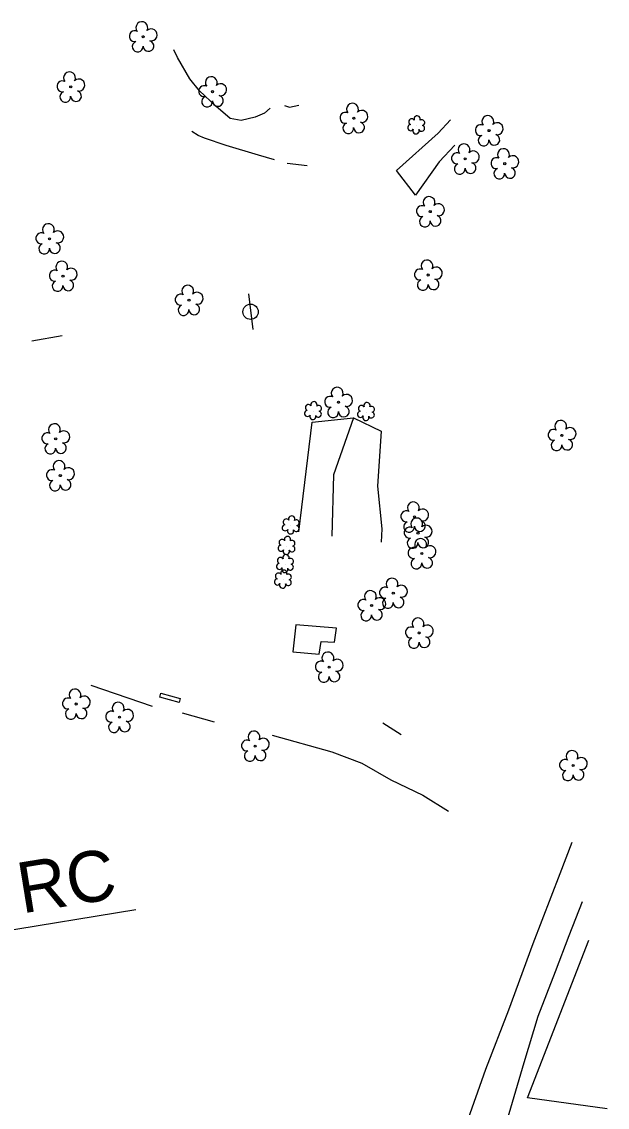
# Model space of a CAD drawing. Extents: x 477009 to 479892, y 492858 to 496862.
# Drawn here: x 478502.1 to 478686.6, y 495186.3 to 495528.3 of the extents above; entities that cross this region are included whole.
import ezdxf

# ---------------------------------------------------------------- set-up
doc = ezdxf.new("R2010")
doc.units = 0
for name, color, linetype in [('Exist Horizontal Alignment', 7, 'Continuous'), ('Exist Other Culture Area Outline', 7, 'Continuous'), ('Exist Other Culture Fence Line', 7, 'Continuous'), ('Exist Roads Soil', 7, 'Continuous'), ('Exist Structure Minor Footbridge', 7, 'Continuous'), ('Exist Utilities Telephone Pole CELL', 7, 'Continuous'), ('Exist Vegetation Shrub CELL', 7, 'Continuous'), ('Exist Vegetation Tree CELL', 7, 'Continuous'), ('Exist Vegetation Woods Line', 7, 'Continuous')]:
    doc.layers.add(name, color=color, linetype=linetype)

msp = doc.modelspace()

# ---------------------------------------------------------------- linework, layer by layer
at = {"layer": 'Exist Horizontal Alignment'}
msp.add_line((478419.63, 495229.31), (478538.1, 495248.58), dxfattribs=at)
at = {"layer": 'Exist Other Culture Area Outline'}
msp.add_lwpolyline([(478601.3, 495337.22), (478588.46, 495338.24), (478587.59, 495329.78), (478595.89, 495329.06), (478596.48, 495333.05), (478600.63, 495332.82), (478601.3, 495337.22)], dxfattribs=at)
msp.add_lwpolyline([(478545.97, 495316.74), (478552.07, 495315.1), (478551.72, 495313.82), (478545.62, 495315.47)], close=True, dxfattribs=at)
at = {"layer": 'Exist Other Culture Fence Line'}
for p, q in [((478523.84, 495319.27), (478543.26, 495312.62)), ((478552.63, 495310.53), (478562.77, 495307.68))]:
    msp.add_line(p, q, dxfattribs=at)
for points in [[(478589.46, 495367.53), (478593.68, 495402.09), (478606.68, 495403.45), (478615.38, 495399.29), (478614.21, 495382.01), (478615.58, 495368.49), (478615.39, 495364.34)], [(478606.68, 495403.45), (478600.31, 495385.57), (478599.87, 495366.25)], [(478580.98, 495303.48), (478599.86, 495298.24), (478609.24, 495294.67), (478618.43, 495289.39), (478628.5, 495284.58), (478636.55, 495279.56)]]:
    msp.add_lwpolyline(points, dxfattribs=at)
at = {"layer": 'Exist Roads Soil'}
msp.add_line((478585.78, 495483.78), (478592.07, 495482.97), dxfattribs=at)
for points in [[(478580.44, 495501.12), (478578.62, 495499.49), (478575.62, 495498.29), (478571.31, 495497.22), (478567.83, 495497.82), (478563.25, 495501.67), (478558.08, 495506.54), (478555.07, 495510.34), (478551.15, 495517.05), (478549.99, 495519.47)], [(478584.92, 495501.95), (478586.47, 495501.43), (478589.39, 495502.05)], [(478626.18, 495473.62), (478620.2, 495481.43), (478633.33, 495493.22), (478637.24, 495497.42)], [(478581.72, 495484.77), (478576.73, 495486.22), (478566.51, 495489.33), (478559.67, 495491.6), (478557.69, 495492.43), (478555.7, 495493.76)], [(478638.59, 495489.38), (478633.69, 495484.17), (478626.18, 495473.62)], [(478642.19, 495180.71), (478648.36, 495198.25), (478655.57, 495216.94), (478663.32, 495237.85), (478671.84, 495259.89), (478675.59, 495269.75)], [(478678.75, 495251.02), (478674.49, 495240.27), (478670.25, 495228.92), (478664.72, 495214.87), (478660.36, 495200.31), (478654.61, 495180.64)]]:
    msp.add_lwpolyline(points, dxfattribs=at)
at = {"layer": 'Exist Structure Minor Footbridge'}
for p, q in [((478514.87, 495429.34), (478505.32, 495427.68)), ((478621.68, 495303.62), (478615.9, 495307.26))]:
    msp.add_line(p, q, dxfattribs=at)
at = {"layer": 'Exist Utilities Telephone Pole CELL'}
for p, q in [((478573.52, 495442.54), (478574.94, 495431.29)), ((478574.23, 495436.91), (478574.23, 495436.91))]:
    msp.add_line(p, q, dxfattribs=at)
msp.add_circle((478574.23, 495436.91), 2.41, dxfattribs=at)
at = {"layer": 'Exist Vegetation Shrub CELL'}
for p, q in [((478626.5, 495495.63), (478626.5, 495495.63)), ((478593.96, 495405.6), (478593.96, 495405.6)), ((478610.67, 495405.31), (478610.67, 495405.31)), ((478586.94, 495369.56), (478586.94, 495369.56)), ((478585.63, 495363.1), (478585.63, 495363.1)), ((478585.14, 495357.4), (478585.14, 495357.4)), ((478584.48, 495352.49), (478584.48, 495352.49))]:
    msp.add_line(p, q, dxfattribs=at)
for centre, radius, start, end in [((478624.7, 495494.93), 0.955, 95.1099, 327.9534), ((478625.02, 495496.76), 0.968, 35.8908, 245.4216), ((478626.73, 495497.67), 0.99, 334.8391, 200.4717), ((478628.14, 495494.71), 0.937, 204.9913, 73.4601), ((478628.18, 495496.5), 0.929, 284.4567, 126.0861), ((478626.37, 495493.95), 0.984, 151.2797, 21.387), ((478592.48, 495406.73), 0.968, 35.8908, 245.4216), ((478594.19, 495407.64), 0.99, 334.8391, 200.4717), ((478595.63, 495406.47), 0.929, 284.4567, 126.0861), ((478609.18, 495406.43), 0.968, 35.8908, 245.4216), ((478610.9, 495407.35), 0.99, 334.8391, 200.4717), ((478612.34, 495406.18), 0.929, 284.4567, 126.0861), ((478592.16, 495404.9), 0.955, 95.1099, 327.9534), ((478593.83, 495403.92), 0.984, 151.2797, 21.387), ((478595.6, 495404.68), 0.937, 204.9913, 73.4601), ((478608.87, 495404.6), 0.955, 95.1099, 327.9534), ((478610.54, 495403.62), 0.984, 151.2797, 21.387), ((478612.3, 495404.38), 0.937, 204.9913, 73.4601), ((478587.17, 495371.6), 0.99, 334.8391, 200.4717), ((478585.14, 495368.86), 0.955, 95.1099, 327.9534), ((478585.46, 495370.69), 0.968, 35.8908, 245.4216), ((478588.58, 495368.63), 0.937, 204.9913, 73.4601), ((478588.61, 495370.43), 0.929, 284.4567, 126.0861), ((478585.86, 495365.14), 0.99, 334.8391, 200.4717), ((478586.81, 495367.88), 0.984, 151.2797, 21.387), ((478583.83, 495362.4), 0.955, 95.1099, 327.9534), ((478584.15, 495364.23), 0.968, 35.8908, 245.4216), ((478585.5, 495361.42), 0.984, 151.2797, 21.387), ((478587.27, 495362.17), 0.937, 204.9913, 73.4601), ((478587.3, 495363.97), 0.929, 284.4567, 126.0861), ((478583.65, 495358.53), 0.968, 35.8908, 245.4216), ((478585.37, 495359.44), 0.99, 334.8391, 200.4717), ((478586.81, 495358.27), 0.929, 284.4567, 126.0861), ((478583.34, 495356.69), 0.955, 95.1099, 327.9534), ((478584.71, 495354.53), 0.99, 334.8391, 200.4717), ((478585.01, 495355.72), 0.984, 151.2797, 21.387), ((478586.77, 495356.47), 0.937, 204.9913, 73.4601), ((478582.68, 495351.78), 0.955, 95.1099, 327.9534), ((478583, 495353.62), 0.968, 35.8908, 245.4216), ((478586.12, 495351.56), 0.937, 204.9913, 73.4601), ((478586.15, 495353.36), 0.929, 284.4567, 126.0861), ((478584.35, 495350.81), 0.984, 151.2797, 21.387)]:
    msp.add_arc(centre, radius, start, end, dxfattribs=at)
at = {"layer": 'Exist Vegetation Tree CELL'}
for p, q in [((478540.35, 495523.59), (478540.35, 495523.59)), ((478517.54, 495507.77), (478517.54, 495507.77)), ((478562.21, 495506.28), (478562.21, 495506.28)), ((478606.74, 495497.89), (478606.74, 495497.89)), ((478649.38, 495494), (478649.38, 495494)), ((478641.85, 495485.1), (478641.85, 495485.1)), ((478654.32, 495483.58), (478654.32, 495483.58)), ((478630.86, 495468.48), (478630.86, 495468.48)), ((478510.88, 495459.93), (478510.88, 495459.93)), ((478515.11, 495448.15), (478515.11, 495448.15)), ((478630.21, 495448.5), (478630.21, 495448.5)), ((478554.81, 495440.57), (478554.81, 495440.57)), ((478601.91, 495408.4), (478601.91, 495408.4)), ((478512.8, 495396.9), (478512.8, 495396.9)), ((478672.35, 495397.97), (478672.35, 495397.97)), ((478514.26, 495385.29), (478514.26, 495385.29)), ((478625.89, 495372.3), (478625.89, 495372.3)), ((478626.98, 495367.17), (478626.98, 495367.17)), ((478628.19, 495360.73), (478628.19, 495360.73)), ((478619.21, 495348.26), (478619.21, 495348.26)), ((478612.37, 495344.35), (478612.37, 495344.35)), ((478627.37, 495335.72), (478627.37, 495335.72)), ((478598.97, 495324.96), (478598.97, 495324.96)), ((478519.27, 495313.32), (478519.27, 495313.32)), ((478532.89, 495309.16), (478532.89, 495309.16)), ((478575.67, 495300.07), (478575.67, 495300.07)), ((478675.92, 495293.96), (478675.92, 495293.96))]:
    msp.add_line(p, q, dxfattribs=at)
for centre in [(478540.35, 495523.59), (478517.54, 495507.77), (478562.21, 495506.28), (478606.74, 495497.89), (478649.38, 495494), (478641.85, 495485.1), (478654.32, 495483.58), (478630.86, 495468.48), (478510.88, 495459.93), (478515.11, 495448.15), (478630.21, 495448.5), (478554.81, 495440.57), (478601.91, 495408.4), (478512.8, 495396.9), (478672.35, 495397.97), (478514.26, 495385.29), (478625.89, 495372.3), (478626.98, 495367.17), (478628.19, 495360.73), (478619.21, 495348.26), (478612.37, 495344.35), (478627.37, 495335.72), (478598.97, 495324.96), (478519.27, 495313.32), (478532.89, 495309.16), (478575.67, 495300.07), (478675.92, 495293.96)]:
    msp.add_circle(centre, 0.326, dxfattribs=at)
for centre, radius, start, end in [((478539.96, 495526.46), 1.86, 330.1651, 219.7134), ((478542.89, 495524.18), 1.9, 257.1011, 134.1999), ((478537.74, 495523.75), 1.73, 62.6636, 279.3457), ((478538.64, 495520.47), 1.69, 111.5671, 6.231), ((478542.02, 495520.69), 1.7, 181.2822, 74.56), ((478517.16, 495510.65), 1.86, 330.1651, 219.7134), ((478514.93, 495507.93), 1.73, 62.6636, 279.3457), ((478520.09, 495508.36), 1.9, 257.1011, 134.1999), ((478561.83, 495509.15), 1.86, 330.1651, 219.7134), ((478515.84, 495504.65), 1.69, 111.5671, 6.231), ((478519.21, 495504.88), 1.7, 181.2822, 74.56), ((478559.61, 495506.43), 1.73, 62.6636, 279.3457), ((478564.76, 495506.87), 1.9, 257.1011, 134.1999), ((478560.51, 495503.16), 1.69, 111.5671, 6.231), ((478563.89, 495503.38), 1.7, 181.2822, 74.56), ((478606.35, 495500.76), 1.86, 330.1651, 219.7134), ((478604.13, 495498.04), 1.73, 62.6636, 279.3457), ((478609.29, 495498.48), 1.9, 257.1011, 134.1999), ((478649, 495496.87), 1.86, 330.1651, 219.7134), ((478605.03, 495494.77), 1.69, 111.5671, 6.231), ((478608.41, 495494.99), 1.7, 181.2822, 74.56), ((478646.78, 495494.15), 1.73, 62.6636, 279.3457), ((478651.93, 495494.59), 1.9, 257.1011, 134.1999), ((478647.68, 495490.88), 1.69, 111.5671, 6.231), ((478651.06, 495491.1), 1.7, 181.2822, 74.56), ((478641.47, 495487.98), 1.86, 330.1651, 219.7134), ((478639.25, 495485.26), 1.73, 62.6636, 279.3457), ((478644.4, 495485.69), 1.9, 257.1011, 134.1999), ((478651.72, 495483.74), 1.73, 62.6636, 279.3457), ((478653.94, 495486.46), 1.86, 330.1651, 219.7134), ((478656.87, 495484.17), 1.9, 257.1011, 134.1999), ((478640.15, 495481.98), 1.69, 111.5671, 6.231), ((478643.53, 495482.2), 1.7, 181.2822, 74.56), ((478652.62, 495480.46), 1.69, 111.5671, 6.231), ((478655.99, 495480.68), 1.7, 181.2822, 74.56), ((478630.47, 495471.36), 1.86, 330.1651, 219.7134), ((478628.25, 495468.64), 1.73, 62.6636, 279.3457), ((478633.41, 495469.07), 1.9, 257.1011, 134.1999), ((478510.49, 495462.81), 1.86, 330.1651, 219.7134), ((478629.15, 495465.36), 1.69, 111.5671, 6.231), ((478632.53, 495465.58), 1.7, 181.2822, 74.56), ((478508.27, 495460.09), 1.73, 62.6636, 279.3457), ((478513.43, 495460.52), 1.9, 257.1011, 134.1999), ((478509.17, 495456.81), 1.69, 111.5671, 6.231), ((478512.55, 495457.03), 1.7, 181.2822, 74.56), ((478514.73, 495451.02), 1.86, 330.1651, 219.7134), ((478629.82, 495451.38), 1.86, 330.1651, 219.7134), ((478632.76, 495449.09), 1.9, 257.1011, 134.1999), ((478512.51, 495448.3), 1.73, 62.6636, 279.3457), ((478517.66, 495448.74), 1.9, 257.1011, 134.1999), ((478627.6, 495448.66), 1.73, 62.6636, 279.3457), ((478513.41, 495445.03), 1.69, 111.5671, 6.231), ((478516.79, 495445.25), 1.7, 181.2822, 74.56), ((478554.43, 495443.44), 1.86, 330.1651, 219.7134), ((478628.5, 495445.38), 1.69, 111.5671, 6.231), ((478631.88, 495445.6), 1.7, 181.2822, 74.56), ((478552.21, 495440.72), 1.73, 62.6636, 279.3457), ((478557.36, 495441.16), 1.9, 257.1011, 134.1999), ((478553.11, 495437.45), 1.69, 111.5671, 6.231), ((478556.48, 495437.67), 1.7, 181.2822, 74.56), ((478599.31, 495408.56), 1.73, 62.6636, 279.3457), ((478601.53, 495411.28), 1.86, 330.1651, 219.7134), ((478604.46, 495408.99), 1.9, 257.1011, 134.1999), ((478600.21, 495405.28), 1.69, 111.5671, 6.231), ((478603.59, 495405.5), 1.7, 181.2822, 74.56), ((478512.41, 495399.77), 1.86, 330.1651, 219.7134), ((478669.75, 495398.13), 1.73, 62.6636, 279.3457), ((478671.97, 495400.85), 1.86, 330.1651, 219.7134), ((478674.9, 495398.56), 1.9, 257.1011, 134.1999), ((478510.19, 495397.05), 1.73, 62.6636, 279.3457), ((478515.35, 495397.49), 1.9, 257.1011, 134.1999), ((478670.65, 495394.85), 1.69, 111.5671, 6.231), ((478674.02, 495395.07), 1.7, 181.2822, 74.56), ((478511.1, 495393.78), 1.69, 111.5671, 6.231), ((478514.47, 495394), 1.7, 181.2822, 74.56), ((478513.88, 495388.17), 1.86, 330.1651, 219.7134), ((478511.66, 495385.45), 1.73, 62.6636, 279.3457), ((478516.81, 495385.88), 1.9, 257.1011, 134.1999), ((478512.56, 495382.17), 1.69, 111.5671, 6.231), ((478515.94, 495382.4), 1.7, 181.2822, 74.56), ((478625.51, 495375.17), 1.86, 330.1651, 219.7134), ((478623.29, 495372.45), 1.73, 62.6636, 279.3457), ((478628.44, 495372.88), 1.9, 257.1011, 134.1999), ((478624.19, 495369.17), 1.69, 111.5671, 6.231), ((478624.38, 495367.33), 1.73, 62.6636, 279.3457), ((478626.6, 495370.05), 1.86, 330.1651, 219.7134), ((478627.57, 495369.4), 1.7, 181.2822, 74.56), ((478629.53, 495367.76), 1.9, 257.1011, 134.1999), ((478625.28, 495364.05), 1.69, 111.5671, 6.231), ((478627.8, 495363.6), 1.86, 330.1651, 219.7134), ((478628.65, 495364.28), 1.7, 181.2822, 74.56), ((478625.58, 495360.89), 1.73, 62.6636, 279.3457), ((478630.74, 495361.32), 1.9, 257.1011, 134.1999), ((478626.49, 495357.61), 1.69, 111.5671, 6.231), ((478629.86, 495357.83), 1.7, 181.2822, 74.56), ((478618.82, 495351.13), 1.86, 330.1651, 219.7134), ((478611.99, 495347.22), 1.86, 330.1651, 219.7134), ((478616.6, 495348.41), 1.73, 62.6636, 279.3457), ((478621.75, 495348.85), 1.9, 257.1011, 134.1999), ((478609.77, 495344.5), 1.73, 62.6636, 279.3457), ((478614.92, 495344.94), 1.9, 257.1011, 134.1999), ((478617.5, 495345.14), 1.69, 111.5671, 6.231), ((478620.88, 495345.36), 1.7, 181.2822, 74.56), ((478610.67, 495341.23), 1.69, 111.5671, 6.231), ((478614.05, 495341.45), 1.7, 181.2822, 74.56), ((478626.99, 495338.6), 1.86, 330.1651, 219.7134), ((478629.92, 495336.31), 1.9, 257.1011, 134.1999), ((478624.77, 495335.88), 1.73, 62.6636, 279.3457), ((478625.67, 495332.6), 1.69, 111.5671, 6.231), ((478629.04, 495332.82), 1.7, 181.2822, 74.56), ((478598.59, 495327.83), 1.86, 330.1651, 219.7134), ((478596.37, 495325.11), 1.73, 62.6636, 279.3457), ((478601.52, 495325.55), 1.9, 257.1011, 134.1999), ((478597.27, 495321.84), 1.69, 111.5671, 6.231), ((478600.64, 495322.06), 1.7, 181.2822, 74.56), ((478518.89, 495316.2), 1.86, 330.1651, 219.7134), ((478516.67, 495313.48), 1.73, 62.6636, 279.3457), ((478521.82, 495313.91), 1.9, 257.1011, 134.1999), ((478517.57, 495310.2), 1.69, 111.5671, 6.231), ((478520.94, 495310.42), 1.7, 181.2822, 74.56), ((478530.28, 495309.31), 1.73, 62.6636, 279.3457), ((478532.5, 495312.03), 1.86, 330.1651, 219.7134), ((478535.44, 495309.75), 1.9, 257.1011, 134.1999), ((478531.18, 495306.04), 1.69, 111.5671, 6.231), ((478534.56, 495306.26), 1.7, 181.2822, 74.56), ((478575.29, 495302.95), 1.86, 330.1651, 219.7134), ((478573.07, 495300.23), 1.73, 62.6636, 279.3457), ((478578.22, 495300.66), 1.9, 257.1011, 134.1999), ((478573.97, 495296.95), 1.69, 111.5671, 6.231), ((478577.35, 495297.17), 1.7, 181.2822, 74.56), ((478675.53, 495296.83), 1.86, 330.1651, 219.7134), ((478673.31, 495294.11), 1.73, 62.6636, 279.3457), ((478678.46, 495294.55), 1.9, 257.1011, 134.1999), ((478674.21, 495290.84), 1.69, 111.5671, 6.231), ((478677.59, 495291.06), 1.7, 181.2822, 74.56)]:
    msp.add_arc(centre, radius, start, end, dxfattribs=at)
at = {"layer": 'Exist Vegetation Woods Line'}
msp.add_lwpolyline([(478686.65, 495185.79), (478661.53, 495189.23), (478680.79, 495238.88)], dxfattribs=at)

# ---------------------------------------------------------------- texts
at = {"layer": 'Exist Horizontal Alignment'}
msp.add_text('PRC', height=16, rotation=9.2405, dxfattribs=at).set_placement((478488.09, 495244.99))

doc.saveas('drawing.dxf')
